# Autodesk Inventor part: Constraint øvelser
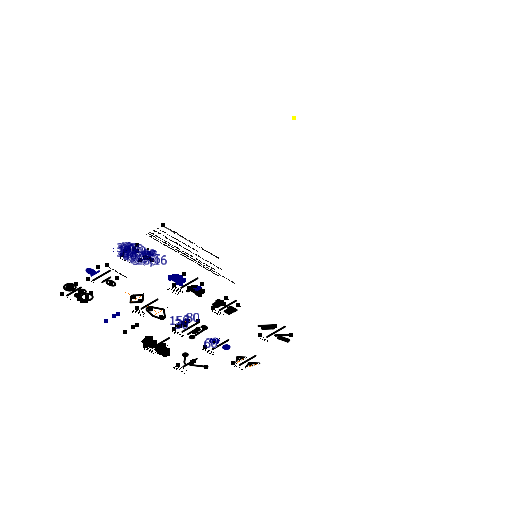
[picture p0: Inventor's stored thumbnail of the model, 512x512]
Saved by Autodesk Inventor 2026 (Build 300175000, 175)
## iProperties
Created: 2013-10
Part Number: Constraint øvelser
Material: Generic
Document SubType Name: Modeling
Designer: Cadskolen
Density: 1 g/cm^3
Appearance: Default
Author: Cadskolen
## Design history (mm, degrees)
sketch "Sketch1"
  geometry: L1 (743.982, -3419.561)-(743.982, -3735.393); L2 (553.275, -3681.623)-(588.275, -3681.623); L3 (588.275, -3681.623)-(588.275, -3686.623); L4 (588.275, -3686.623)-(553.275, -3686.623); L5 (553.275, -3686.623)-(553.275, -3681.623); L6 (558.275, -3681.623)-(583.275, -3681.623); L7 (583.275, -3681.623)-(583.275, -3601.623); L8 (558.275, -3601.623)-(558.275, -3681.623); L9 (685.755, -3561.24)-(675.751, -3561.24); L10 (558.275, -3621.623)-(523.275, -3621.623); L11 (523.275, -3621.623)-(523.275, -3651.623); L12 (523.275, -3651.623)-(558.275, -3651.623); L13 (558.275, -3651.623)-(558.275, -3621.623); L14 (533.275, -3621.623)-(529.275, -3621.623); L15 (529.275, -3621.623)-(529.275, -3581.623); L16 (529.275, -3581.623)-(533.275, -3581.623); L17 (533.275, -3581.623)-(533.275, -3621.623); L18 (688.253, -3569.24)-(688.253, -3561.24); L19 (688.253, -3561.24)-(673.253, -3561.24); L20 (673.253, -3561.24)-(673.253, -3569.24); L21 (673.253, -3569.24)-(688.253, -3569.24); L22 (688.253, -3569.24)-(673.253, -3561.24); L23 (688.253, -3561.24)-(673.253, -3569.24); L24 (583.275, -3681.623)-(558.275, -3681.623); L25 (575.775, -3562.787)-(575.775, -3601.623); L26 (575.775, -3601.623)-(565.775, -3601.623); L27 (565.775, -3601.623)-(565.775, -3562.787); L28 (558.275, -3601.623)-(583.275, -3601.623); L29 (976.564, -3562.848)-(934.545, -3562.848); L30 (934.545, -3562.848)-(949.556, -3578.82); L31 (949.556, -3578.82)-(976.564, -3570.848); L32 (976.564, -3570.848)-(934.545, -3562.848); L33 (976.564, -3570.848)-(976.564, -3562.848); L34 (976.564, -3562.848)-(949.556, -3578.82); L35 (960.575, -3562.848)-(950.534, -3562.848); L36 (851.646, -3577.076)-(855.313, -3596.535); L37 (845.486, -3598.387)-(841.819, -3578.928); L38 (830.83, -3601.149)-(869.969, -3593.774); L39 (855.313, -3596.535)-(845.486, -3598.387); L40 (801.83, -3577.477)-(808.712, -3577.477); L41 (808.712, -3577.477)-(805.83, -3614.945); L42 (801.83, -3614.945)-(801.83, -3577.477); L43 (805.83, -3614.945)-(801.83, -3614.945); L44 (830.83, -3614.945)-(786.594, -3614.945); L45 (825.83, -3673.28)-(860.83, -3673.28); L46 (860.83, -3673.28)-(860.83, -3678.28); L47 (860.83, -3678.28)-(825.83, -3678.28); L48 (825.83, -3678.28)-(825.83, -3673.28); L49 (786.594, -3614.945)-(795.576, -3643.875); L50 (795.576, -3643.875)-(830.83, -3636.623); L51 (830.83, -3636.623)-(830.83, -3614.945); L52 (855.83, -3673.28)-(869.969, -3593.774); L53 (830.83, -3601.149)-(830.83, -3673.28); L54 (830.83, -3673.28)-(855.83, -3673.28); L55 (855.83, -3673.28)-(830.83, -3673.28); L56 (1600.578, -3669.394)-(1600.578, -3642.265) reference; L57 (1403.889, -3669.394)-(1403.889, -3642.265) reference; L58 (1590.404, -3693.133)-(1597.187, -3686.35) reference; L59 (1393.715, -3679.568)-(1610.751, -3679.568) reference; L60 (1603.969, -3686.35)-(1400.497, -3686.35) reference; L61 (1400.497, -3672.786)-(1603.969, -3672.786) reference; L62 (1437.8, -3693.133)-(1437.8, -3720.262) reference; L63 (1434.409, -3720.262)-(1434.409, -3693.133) reference; L64 (1431.018, -3693.133)-(1431.018, -3720.262) reference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; C1 r 9.652 at (1563.351, -3655.821) reference; C2 r 9.652 at (1584.716, -3655.821) reference; C3 r 9.652 at (1441.115, -3655.821) reference; C4 r 9.652 at (1419.75, -3655.821) reference; C5 r 9.652 at (1789.919, -3646.849); C6 r 9.652 at (1768.477, -3655.318); C7 r 9.652 at (1933.443, -3655.318); C8 r 9.652 at (1912.002, -3649.392); C9 r 26.096 at (2491.958, -3678.28); C10 r 26.096 at (2267.381, -3678.28); C11 r 40 at (578.649, -4313.757); C12 r 12.176 at (946.759, -4312.539); C13 r 17.093 at (1378.264, -4324.354); C14 r 17.093 at (1493.366, -4324.354); C15 r 24.277 at (1731.89, -4366.267); C16 r 18.788 at (1962.66, -4394.28); C17 r 51.962 at (2822.386, -4283.823); C18 r 19.53 at (2822.386, -4283.823); C19 r 19.53 at (3030.545, -4270.92) reference; C20 r 39.059 at (3030.545, -4270.92) reference; C21 r 20.994 at (635.558, -4756.667); C22 r 33.615 at (635.558, -4756.667); C23 r 44.683 at (635.558, -4756.667); C24 r 75.612 at (635.558, -4756.667); C25 r 13.816 at (635.558, -4756.667); C26 r 8.349 at (635.558, -4756.667); C27 r 8.349 at (1009.27, -4832.279); C28 r 13.816 at (968.594, -4857.184); C29 r 20.994 at (914.354, -4861.24); C30 r 75.612 at (948.104, -4756.667); C31 r 33.615 at (834.4, -4815.195); C32 r 44.683 at (819.775, -4711.918); C33 r 30.53 at (2773.629, -4768.956); C34 r 17.49 at (3156.485, -4768.956); A1 r 50 centre (625.775, -3562.787) between (675.751, -3561.24) and (575.775, -3562.787); A2 r 60 centre (625.775, -3562.787) between (685.755, -3561.24) and (565.775, -3562.787); A3 r 50 centre (900.781, -3567.817) between (950.534, -3562.848) and (851.646, -3577.076); A4 r 60 centre (900.781, -3567.817) between (960.575, -3562.848) and (841.819, -3578.928); A5 r 22.108 centre (1524.276, -3654.134) between (1542.927, -3666.003) and (1542.927, -3642.265) reference; A6 r 22.108 centre (1480.19, -3654.134) between (1461.539, -3642.265) and (1461.539, -3666.003) reference; A7 r 6.782 centre (1400.497, -3679.568) between (1400.497, -3672.786) and (1400.497, -3686.35) reference; A8 r 6.782 centre (1603.969, -3679.568) between (1603.969, -3686.35) and (1603.969, -3672.786) reference; A9 r 1331.043 centre (1502.233, -4966.526) between (1597.187, -3638.874) and (1407.28, -3638.874) reference; A10 r 1237.786 centre (1502.233, -4817.53) between (1574.408, -3581.851) and (1430.078, -3581.85) reference; A11 r 1237.786 centre (1502.233, -4815.618) between (1573.615, -3579.892) and (1430.91, -3579.889) reference; A12 r 1103.835 centre (1503.929, -4735.925) between (1502.233, -3632.091) and (1417.453, -3635.482) reference; A13 r 4.796 centre (1424.932, -3622.673) between (1420.267, -3621.559) and (1425.761, -3627.396) reference; A14 r 4.796 centre (1437.8, -3589.231) between (1437.179, -3584.476) and (1433.456, -3587.199) reference; A15 r 1103.835 centre (1500.538, -4735.925) between (1587.013, -3635.482) and (1502.233, -3632.091) reference; A16 r 1.696 centre (1514.102, -3593.093) between (1514.208, -3594.785) and (1515.793, -3593.223) reference; A17 r 1.696 centre (1514.102, -3589.701) between (1515.797, -3589.645) and (1514.209, -3588.009) reference; A18 r 1.696 centre (1490.364, -3593.093) between (1488.673, -3593.223) and (1490.259, -3594.785) reference; A19 r 1.696 centre (1490.364, -3589.701) between (1490.257, -3588.009) and (1488.669, -3589.645) reference; A20 r 4.796 centre (1566.679, -3589.263) between (1571.024, -3587.233) and (1567.303, -3584.508) reference; A21 r 4.796 centre (1579.534, -3622.709) between (1578.703, -3627.432) and (1584.2, -3621.597) reference; A22 r 4.796 centre (1773.659, -3622.17) between (1768.994, -3621.056) and (1774.488, -3626.894); A23 r 4.796 centre (1786.528, -3588.728) between (1785.906, -3583.973) and (1782.183, -3586.696); A24 r 1103.835 centre (1852.656, -4735.422) between (1850.96, -3631.588) and (1766.18, -3634.98); A25 r 6.782 centre (1952.696, -3679.065) between (1952.696, -3685.847) and (1952.696, -3672.283); A26 r 4.796 centre (1915.406, -3588.76) between (1919.751, -3586.73) and (1916.03, -3584.005); A27 r 4.796 centre (1928.261, -3622.206) between (1927.43, -3626.929) and (1932.927, -3621.095); A28 r 22.108 centre (1873.003, -3653.631) between (1891.655, -3665.5) and (1891.655, -3641.762); A29 r 1103.835 centre (1849.265, -4735.422) between (1935.74, -3634.98) and (1850.96, -3631.588); A30 r 22.108 centre (1828.917, -3653.631) between (1810.266, -3641.762) and (1810.266, -3665.5); A31 r 1331.043 centre (1850.96, -4966.023) between (1945.914, -3638.371) and (1756.007, -3638.371); A32 r 1237.786 centre (1850.96, -4817.027) between (1923.135, -3581.348) and (1778.805, -3581.347); A33 r 1237.786 centre (1850.96, -4815.115) between (1922.342, -3579.389) and (1779.637, -3579.386); A34 r 6.782 centre (1749.224, -3679.065) between (1749.224, -3672.283) and (1749.224, -3685.847); A35 r 34.582 centre (1378.264, -4324.354) between (1352.406, -4301.391) and (1352.406, -4347.317); A36 r 34.582 centre (1493.366, -4324.354) between (1519.225, -4347.317) and (1519.225, -4301.391); A37 r 53.437 centre (1731.89, -4366.267) between (1708.315, -4318.311) and (1720.121, -4418.392); A38 r 53.437 centre (1943.273, -4387.325) between (1988.375, -4415.984) and (1962.66, -4337.528); A39 r 40 centre (2250.668, -4216.267) between (2290.668, -4216.267) and (2210.668, -4216.267); A40 r 15 centre (2250.668, -4216.267) between (2265.668, -4216.267) and (2235.668, -4216.267); A41 r 15 centre (2250.668, -4366.267) between (2235.668, -4366.267) and (2265.668, -4366.267); A42 r 40 centre (2250.668, -4366.267) between (2210.668, -4366.267) and (2290.668, -4366.267); A43 r 40.672 centre (2516.769, -4172.429) between (2556.731, -4164.864) and (2476.809, -4180.002); A44 r 17.434 centre (2491.958, -4246.58) between (2509.2, -4244.001) and (2479.917, -4233.971); A45 r 12.43 centre (2489.435, -4326.985) between (2477.012, -4326.595) and (2501.859, -4327.375); A46 r 31.824 centre (2551.359, -4424.827) between (2530.362, -4448.743) and (2572.955, -4401.452); A47 r 92.388 centre (2946.251, -4828.426) between (2876.094, -4888.54) and (2946.251, -4920.815); A48 r 95.814 centre (2949.671, -4792.735) between (2946.251, -4888.488) and (3003.197, -4872.204); A49 r 1.696 centre (1839.097, -3592.554) between (1837.407, -3592.684) and (1838.992, -3594.246) reference; A50 r 1.696 centre (1839.097, -3589.162) between (1838.99, -3587.47) and (1837.402, -3589.106) reference; A51 r 1.696 centre (1862.836, -3592.554) between (1862.941, -3594.246) and (1864.526, -3592.684) reference; A52 r 1.696 centre (1862.836, -3589.162) between (1864.53, -3589.106) and (1862.942, -3587.47) reference; 69 further points; 2 other entities
  constraints: 636 end point, 117 point on circle, 86 centre point, 64 point on line, 50 horizontal, 47 vertical, 45 parallel, 36 perpendicular, 29 midpoint, 21 tangent, 18 coincident, 8 collinear, 5 concentric, 4 vertical alignment, 3 horizontal alignment, 2 equal radius, 1 line through centre, 379 other
  dimensions: "d382" = 15 distance of L20.end L18.start; "d383" = 8 distance of L18.start L18.end; "d384" = 10 radial gap between concentric circles of A1 A2; "d385" = 4 distance of L15.end L16.end; "d386" = 30 distance of L10.end L11.end; "d387" = 35 distance between parallel lines of L11 L8; "d388" = 25 distance between parallel lines of L7 L8; "d389" = 35 distance of L3.end L4.end; "d390" = 5 distance of L2.end L3.end; "d391" = 25 distance between parallel lines of L17 L8; "d392" = 40 distance between parallel lines of L10 L16; "d393" = 50 radius of A1; "d394" = 28.16 distance of L30.end L31.end; "d395" = 8 distance of L31.end L29.start; "d396" = 10 radial gap between concentric circles of A3 A4; "d397" = 6.88178 distance of L40.start L40.end; "d398" = 30.2922 distance of L44.end L49.end; "d401" = 35 distance of L46.end L47.end; "d402" = 5 distance of L45.end L46.end; "d405" = 50 radius of A3; "d406" = 80 distance of L6.end L7.end; "d407" = 80.75375 distance of L52.start L38.end; "d409" = 20 distance between parallel lines of L10 L28; "d410" = 25 distance of L52.start L53.end; "d411" = 13.79645 distance of L38.start L44.start; "d412" = 40.4475 distance of L44.end L40.start; "d413" = 45.90809 distance of L49.end L53.end; "d414" = 28.5542 distance of L41.end L38.start; "d419" = 80 distance between parallel lines of L270 L271; "d420" = 150 distance of A42.centre A39.centre; "d421" = 30 distance between parallel lines of L274 L273; "d422" = 60 distance of L282.end L283.end
other parameters: "d399" = 35, "d400" = 25, "d403" = 25
